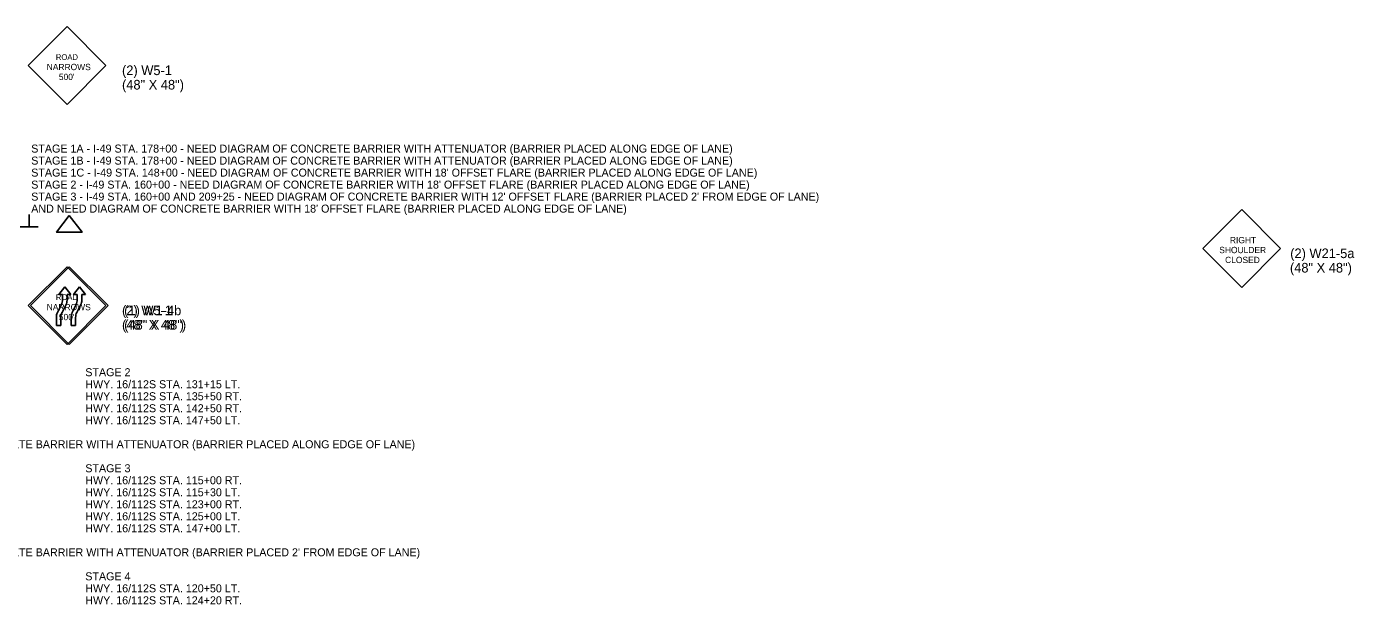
# Model space of a CAD drawing. Extents: x 659657 to 668193, y 633084 to 648639.
# Drawn here: x 662402 to 663232, y 640063 to 640424 of the extents above; entities that cross this region are included whole.
import ezdxf

# ---------------------------------------------------------------- set-up
doc = ezdxf.new("R2010")
doc.units = 0
for name, color, linetype in [('R_Draft', 7, 'Continuous'), ('R_ROW Annot', 7, 'Continuous'), ('T_Notes', 7, 'Continuous'), ('T_SIGNAL CONTROL CABINET', 7, 'Continuous'), ('TEMP_DETECTION ZONE_Stage 2', 7, 'Continuous'), ('TEMP_SIGNAL_HEAD_STAGE 2', 7, 'Continuous'), ('TEXT_TEMP_SIGNAL_POLES_STAGE 2', 7, 'Continuous')]:
    doc.layers.add(name, color=color, linetype=linetype)

msp = doc.modelspace()

# ---------------------------------------------------------------- linework, layer by layer
at = {"layer": 'R_Draft'}
for p, q in [((662427.51, 640424.16), (662403.19, 640399.84)), ((662451.83, 640399.84), (662427.51, 640424.16)), ((662427.51, 640375.54), (662403.19, 640399.84)), ((662451.83, 640399.84), (662427.51, 640375.54)), ((662403.9, 640299.15), (662403.9, 640306.83)), ((662409.5, 640298.99), (662398.25, 640298.99)), ((662404.59, 640249.84), (662428.9, 640274.15)), ((662453.19, 640249.84), (662428.9, 640274.15)), ((662426.08, 640261.5), (662422.3, 640256.79)), ((662429.86, 640256.79), (662426.08, 640261.5)), ((662435.27, 640261.5), (662431.49, 640256.79)), ((662439.04, 640256.79), (662435.27, 640261.5)), ((662423.98, 640250.5), (662421.51, 640245.5)), ((662422.3, 640256.79), (662424.66, 640256.79)), ((662424.66, 640256.79), (662424.66, 640253.56)), ((662427.5, 640253.33), (662427.5, 640256.79)), ((662427.5, 640256.79), (662429.86, 640256.79)), ((662433.17, 640250.5), (662430.69, 640245.5)), ((662431.49, 640256.79), (662433.85, 640256.79)), ((662433.85, 640256.79), (662433.85, 640253.56)), ((662436.68, 640253.33), (662436.68, 640256.79)), ((662436.68, 640256.79), (662439.04, 640256.79)), ((662428.9, 640225.53), (662404.59, 640249.84)), ((662420.83, 640242.44), (662420.83, 640237.32)), ((662423.66, 640237.32), (662423.66, 640242.44)), ((662424.4, 640245.62), (662426.76, 640250.15)), ((662428.9, 640225.53), (662453.19, 640249.84)), ((662430.01, 640242.44), (662430.01, 640237.32)), ((662432.85, 640237.32), (662432.85, 640242.44)), ((662433.59, 640245.62), (662435.94, 640250.15)), ((662420.83, 640237.32), (662423.66, 640237.32)), ((662430.01, 640237.32), (662432.85, 640237.32))]:
    msp.add_line(p, q, dxfattribs=at)
msp.add_lwpolyline([(662428.9, 640306.22), (662436.86, 640295.62), (662420.95, 640295.62)], close=True, dxfattribs=at)
for centre, major_axis, start_param in [((662417.61, 640253.41), (7.05, 0), 5.839651), ((662420.45, 640253.17), (7.05, 0), 5.820525), ((662426.8, 640253.41), (7.05, 0), 5.839651), ((662429.63, 640253.17), (7.05, 0), 5.820525), ((662427.88, 640242.59), (-7.05, 0), 5.839651), ((662430.72, 640242.59), (-7.05, 0), 5.820525), ((662437.07, 640242.59), (-7.05, 0), 5.839651), ((662439.9, 640242.59), (-7.05, 0), 5.820525)]:
    msp.add_ellipse(centre, major_axis=major_axis, ratio=0.96, start_param=start_param, end_param=6.306311, dxfattribs=at)
at = {"layer": 'R_ROW Annot'}
for p, q in [((662403.9, 640299.15), (662403.9, 640306.83)), ((662409.5, 640298.99), (662398.25, 640298.99)), ((662404.59, 640249.84), (662428.9, 640274.15)), ((662453.19, 640249.84), (662428.9, 640274.15)), ((662426.08, 640261.5), (662422.3, 640256.79)), ((662429.86, 640256.79), (662426.08, 640261.5)), ((662435.27, 640261.5), (662431.49, 640256.79)), ((662439.04, 640256.79), (662435.27, 640261.5)), ((662423.98, 640250.5), (662421.51, 640245.5)), ((662422.3, 640256.79), (662424.66, 640256.79)), ((662424.66, 640256.79), (662424.66, 640253.56)), ((662427.5, 640253.33), (662427.5, 640256.79)), ((662427.5, 640256.79), (662429.86, 640256.79)), ((662433.17, 640250.5), (662430.69, 640245.5)), ((662431.49, 640256.79), (662433.85, 640256.79)), ((662433.85, 640256.79), (662433.85, 640253.56)), ((662436.68, 640253.33), (662436.68, 640256.79)), ((662436.68, 640256.79), (662439.04, 640256.79)), ((662428.9, 640225.53), (662404.59, 640249.84)), ((662420.83, 640242.44), (662420.83, 640237.32)), ((662423.66, 640237.32), (662423.66, 640242.44)), ((662424.4, 640245.62), (662426.76, 640250.15)), ((662428.9, 640225.53), (662453.19, 640249.84)), ((662430.01, 640242.44), (662430.01, 640237.32)), ((662432.85, 640237.32), (662432.85, 640242.44)), ((662433.59, 640245.62), (662435.94, 640250.15)), ((662420.83, 640237.32), (662423.66, 640237.32)), ((662430.01, 640237.32), (662432.85, 640237.32))]:
    msp.add_line(p, q, dxfattribs=at)
msp.add_lwpolyline([(662428.9, 640306.22), (662436.86, 640295.62), (662420.95, 640295.62)], close=True, dxfattribs=at)
for centre, major_axis, start_param in [((662417.61, 640253.41), (7.05, 0), 5.839651), ((662420.45, 640253.17), (7.05, 0), 5.820525), ((662426.8, 640253.41), (7.05, 0), 5.839651), ((662429.63, 640253.17), (7.05, 0), 5.820525), ((662427.88, 640242.59), (-7.05, 0), 5.839651), ((662430.72, 640242.59), (-7.05, 0), 5.820525), ((662437.07, 640242.59), (-7.05, 0), 5.839651), ((662439.9, 640242.59), (-7.05, 0), 5.820525)]:
    msp.add_ellipse(centre, major_axis=major_axis, ratio=0.96, start_param=start_param, end_param=6.306311, dxfattribs=at)
at = {"layer": 'T_Notes'}
for p, q in [((662427.51, 640424.16), (662403.19, 640399.84)), ((662451.83, 640399.84), (662427.51, 640424.16)), ((662427.51, 640375.54), (662403.19, 640399.84)), ((662451.83, 640399.84), (662427.51, 640375.54)), ((662403.9, 640299.15), (662403.9, 640306.83)), ((662409.5, 640298.99), (662398.25, 640298.99)), ((662404.59, 640249.84), (662428.9, 640274.15)), ((662453.19, 640249.84), (662428.9, 640274.15)), ((662426.08, 640261.5), (662422.3, 640256.79)), ((662429.86, 640256.79), (662426.08, 640261.5)), ((662435.27, 640261.5), (662431.49, 640256.79)), ((662439.04, 640256.79), (662435.27, 640261.5)), ((662423.98, 640250.5), (662421.51, 640245.5)), ((662422.3, 640256.79), (662424.66, 640256.79)), ((662424.66, 640256.79), (662424.66, 640253.56)), ((662427.5, 640253.33), (662427.5, 640256.79)), ((662427.5, 640256.79), (662429.86, 640256.79)), ((662433.17, 640250.5), (662430.69, 640245.5)), ((662431.49, 640256.79), (662433.85, 640256.79)), ((662433.85, 640256.79), (662433.85, 640253.56)), ((662436.68, 640253.33), (662436.68, 640256.79)), ((662436.68, 640256.79), (662439.04, 640256.79)), ((662428.9, 640225.53), (662404.59, 640249.84)), ((662420.83, 640242.44), (662420.83, 640237.32)), ((662423.66, 640237.32), (662423.66, 640242.44)), ((662424.4, 640245.62), (662426.76, 640250.15)), ((662428.9, 640225.53), (662453.19, 640249.84)), ((662430.01, 640242.44), (662430.01, 640237.32)), ((662432.85, 640237.32), (662432.85, 640242.44)), ((662433.59, 640245.62), (662435.94, 640250.15)), ((662420.83, 640237.32), (662423.66, 640237.32)), ((662430.01, 640237.32), (662432.85, 640237.32))]:
    msp.add_line(p, q, dxfattribs=at)
msp.add_lwpolyline([(662428.9, 640306.22), (662436.86, 640295.62), (662420.95, 640295.62)], close=True, dxfattribs=at)
for centre, major_axis, start_param in [((662417.61, 640253.41), (7.05, 0), 5.839651), ((662420.45, 640253.17), (7.05, 0), 5.820525), ((662426.8, 640253.41), (7.05, 0), 5.839651), ((662429.63, 640253.17), (7.05, 0), 5.820525), ((662427.88, 640242.59), (-7.05, 0), 5.839651), ((662430.72, 640242.59), (-7.05, 0), 5.820525), ((662437.07, 640242.59), (-7.05, 0), 5.839651), ((662439.9, 640242.59), (-7.05, 0), 5.820525)]:
    msp.add_ellipse(centre, major_axis=major_axis, ratio=0.96, start_param=start_param, end_param=6.306311, dxfattribs=at)
at = {"layer": 'TEMP_DETECTION ZONE_Stage 2'}
for p, q in [((662427.51, 640274.16), (662403.19, 640249.84)), ((662451.83, 640249.84), (662427.51, 640274.16)), ((662427.51, 640225.54), (662403.19, 640249.84)), ((662451.83, 640249.84), (662427.51, 640225.54))]:
    msp.add_line(p, q, dxfattribs=at)
at = {"layer": 'TEMP_SIGNAL_HEAD_STAGE 2'}
for p, q in [((662427.51, 640274.16), (662403.19, 640249.84)), ((662451.83, 640249.84), (662427.51, 640274.16)), ((662427.51, 640225.54), (662403.19, 640249.84)), ((662451.83, 640249.84), (662427.51, 640225.54))]:
    msp.add_line(p, q, dxfattribs=at)
at = {"layer": 'TEXT_TEMP_SIGNAL_POLES_STAGE 2'}
for p, q in [((663161.3, 640309.83), (663136.98, 640285.51)), ((663185.62, 640285.51), (663161.3, 640309.83)), ((663161.3, 640261.21), (663136.98, 640285.51)), ((663185.62, 640285.51), (663161.3, 640261.21)), ((662427.51, 640274.16), (662403.19, 640249.84)), ((662451.83, 640249.84), (662427.51, 640274.16)), ((662427.51, 640225.54), (662403.19, 640249.84)), ((662451.83, 640249.84), (662427.51, 640225.54))]:
    msp.add_line(p, q, dxfattribs=at)

# ---------------------------------------------------------------- texts
at = {"layer": 'R_Draft'}
for s, height, rotation, p in [('NARROWS', 3.94, 359.99857, (662414.8, 640396.93)), ('ROAD', 3.583, 359.99898, (662420.49, 640403.31)), ('(2) W5-1', 6, 359.99853, (662461.83, 640393.84)), ("500'", 3.94, 359.99857, (662422.38, 640390.73)), ('(48" X 48")', 6, 359.99853, (662461.83, 640384.84))]:
    msp.add_text(s, height=height, rotation=rotation, dxfattribs=at).set_placement(p)
for s, p in [('(1) W1-4b', (662463.19, 640243.84)), ('(48" X 48")', (662463.19, 640234.84))]:
    msp.add_text(s, height=6, dxfattribs=at).set_placement(p)
at = {"layer": 'R_ROW Annot'}
for s, p in [('(1) W1-4b', (662463.19, 640243.84)), ('(48" X 48")', (662463.19, 640234.84))]:
    msp.add_text(s, height=6, dxfattribs=at).set_placement(p)
at = {"layer": 'T_Notes'}
for s, height, rotation, p in [('NARROWS', 3.94, 359.99857, (662414.8, 640396.93)), ('ROAD', 3.583, 359.99898, (662420.49, 640403.31)), ('(2) W5-1', 6, 359.99853, (662461.83, 640393.84)), ("500'", 3.94, 359.99857, (662422.38, 640390.73)), ('(48" X 48")', 6, 359.99853, (662461.83, 640384.84))]:
    msp.add_text(s, height=height, rotation=rotation, dxfattribs=at).set_placement(p)
for s, p in [('(1) W1-4b', (662463.19, 640243.84)), ('(48" X 48")', (662463.19, 640234.84))]:
    msp.add_text(s, height=6, dxfattribs=at).set_placement(p)
at = {"layer": 'T_SIGNAL CONTROL CABINET'}
for s, p in [('STAGE 1A - I-49 STA. 178+00 - NEED DIAGRAM OF CONCRETE BARRIER WITH ATTENUATOR (BARRIER PLACED ALONG EDGE OF LANE)', (662405.11, 640345.43)), ('STAGE 1B - I-49 STA. 178+00 - NEED DIAGRAM OF CONCRETE BARRIER WITH ATTENUATOR (BARRIER PLACED ALONG EDGE OF LANE)', (662405.11, 640337.93)), ("STAGE 1C - I-49 STA. 148+00 - NEED DIAGRAM OF CONCRETE BARRIER WITH 18' OFFSET FLARE (BARRIER PLACED ALONG EDGE OF LANE)", (662405.11, 640330.43)), ("STAGE 2 - I-49 STA. 160+00 - NEED DIAGRAM OF CONCRETE BARRIER WITH 18' OFFSET FLARE (BARRIER PLACED ALONG EDGE OF LANE)", (662405.11, 640322.93)), ("STAGE 3 - I-49 STA. 160+00 AND 209+25 - NEED DIAGRAM OF CONCRETE BARRIER WITH 12' OFFSET FLARE (BARRIER PLACED 2' FROM EDGE OF LANE) ", (662405.11, 640315.43)), ("AND NEED DIAGRAM OF CONCRETE BARRIER WITH 18' OFFSET FLARE (BARRIER PLACED ALONG EDGE OF LANE)", (662405.11, 640307.93)), ('STAGE 2', (662438.9, 640205.72)), ('HWY. 16/112S STA. 131+15 LT.', (662438.9, 640198.22)), ('HWY. 16/112S STA. 135+50 RT.', (662438.9, 640190.72)), ('HWY. 16/112S STA. 142+50 RT.', (662438.9, 640183.22)), ('HWY. 16/112S STA. 147+50 LT. ', (662438.9, 640175.72)), ('NEED DIAGRAM OF CONCRETE BARRIER WITH ATTENUATOR (BARRIER PLACED ALONG EDGE OF LANE)', (662303.9, 640160.72)), ('STAGE 3', (662438.9, 640145.72)), ('HWY. 16/112S STA. 115+00 RT.', (662438.9, 640138.22)), ('HWY. 16/112S STA. 115+30 LT.', (662438.9, 640130.72)), ('HWY. 16/112S STA. 123+00 RT.', (662438.9, 640123.22)), ('HWY. 16/112S STA. 125+00 LT.', (662438.9, 640115.72)), ('HWY. 16/112S STA. 147+00 LT.', (662438.9, 640108.22)), ("NEED DIAGRAM OF CONCRETE BARRIER WITH ATTENUATOR (BARRIER PLACED 2' FROM EDGE OF LANE)", (662303.9, 640093.22)), ('STAGE 4', (662438.9, 640078.22)), ('HWY. 16/112S STA. 120+50 LT.', (662438.9, 640070.72)), ('HWY. 16/112S STA. 124+20 RT.', (662438.9, 640063.22))]:
    msp.add_text(s, height=5, dxfattribs=at).set_placement(p)
at = {"layer": 'TEMP_DETECTION ZONE_Stage 2'}
for s, height, rotation, p in [('NARROWS', 3.94, 359.99857, (662414.8, 640246.93)), ('ROAD', 3.583, 359.99898, (662420.49, 640253.31)), ("500'", 3.94, 359.99857, (662422.38, 640240.73)), ('(2) W5-1', 6, 359.99853, (662461.83, 640243.84)), ('(48" X 48")', 6, 359.99853, (662461.83, 640234.84))]:
    msp.add_text(s, height=height, rotation=rotation, dxfattribs=at).set_placement(p)
at = {"layer": 'TEMP_SIGNAL_HEAD_STAGE 2'}
for s, height, rotation, p in [('NARROWS', 3.94, 359.99857, (662414.8, 640246.93)), ('ROAD', 3.583, 359.99898, (662420.49, 640253.31)), ("500'", 3.94, 359.99857, (662422.38, 640240.73)), ('(2) W5-1', 6, 359.99853, (662461.83, 640243.84)), ('(48" X 48")', 6, 359.99853, (662461.83, 640234.84))]:
    msp.add_text(s, height=height, rotation=rotation, dxfattribs=at).set_placement(p)
at = {"layer": 'TEXT_TEMP_SIGNAL_POLES_STAGE 2'}
for s, height, rotation, p in [('RIGHT', 3.94, 359.99898, (663153.91, 640288.8)), ('SHOULDER', 3.94, 359.99857, (663147.27, 640282.6)), ('CLOSED', 3.94, 359.99857, (663150.93, 640276.4)), ('NARROWS', 3.94, 359.99857, (662414.8, 640246.93)), ('ROAD', 3.583, 359.99898, (662420.49, 640253.31)), ("500'", 3.94, 359.99857, (662422.38, 640240.73)), ('(2) W5-1', 6, 359.99853, (662461.83, 640243.84)), ('(48" X 48")', 6, 359.99853, (662461.83, 640234.84))]:
    msp.add_text(s, height=height, rotation=rotation, dxfattribs=at).set_placement(p)
for s, p in [('(2) W21-5a', (663191.59, 640279.51)), ('(48" X 48")', (663191.42, 640270.51))]:
    msp.add_text(s, height=6, dxfattribs=at).set_placement(p)

doc.saveas('drawing.dxf')
